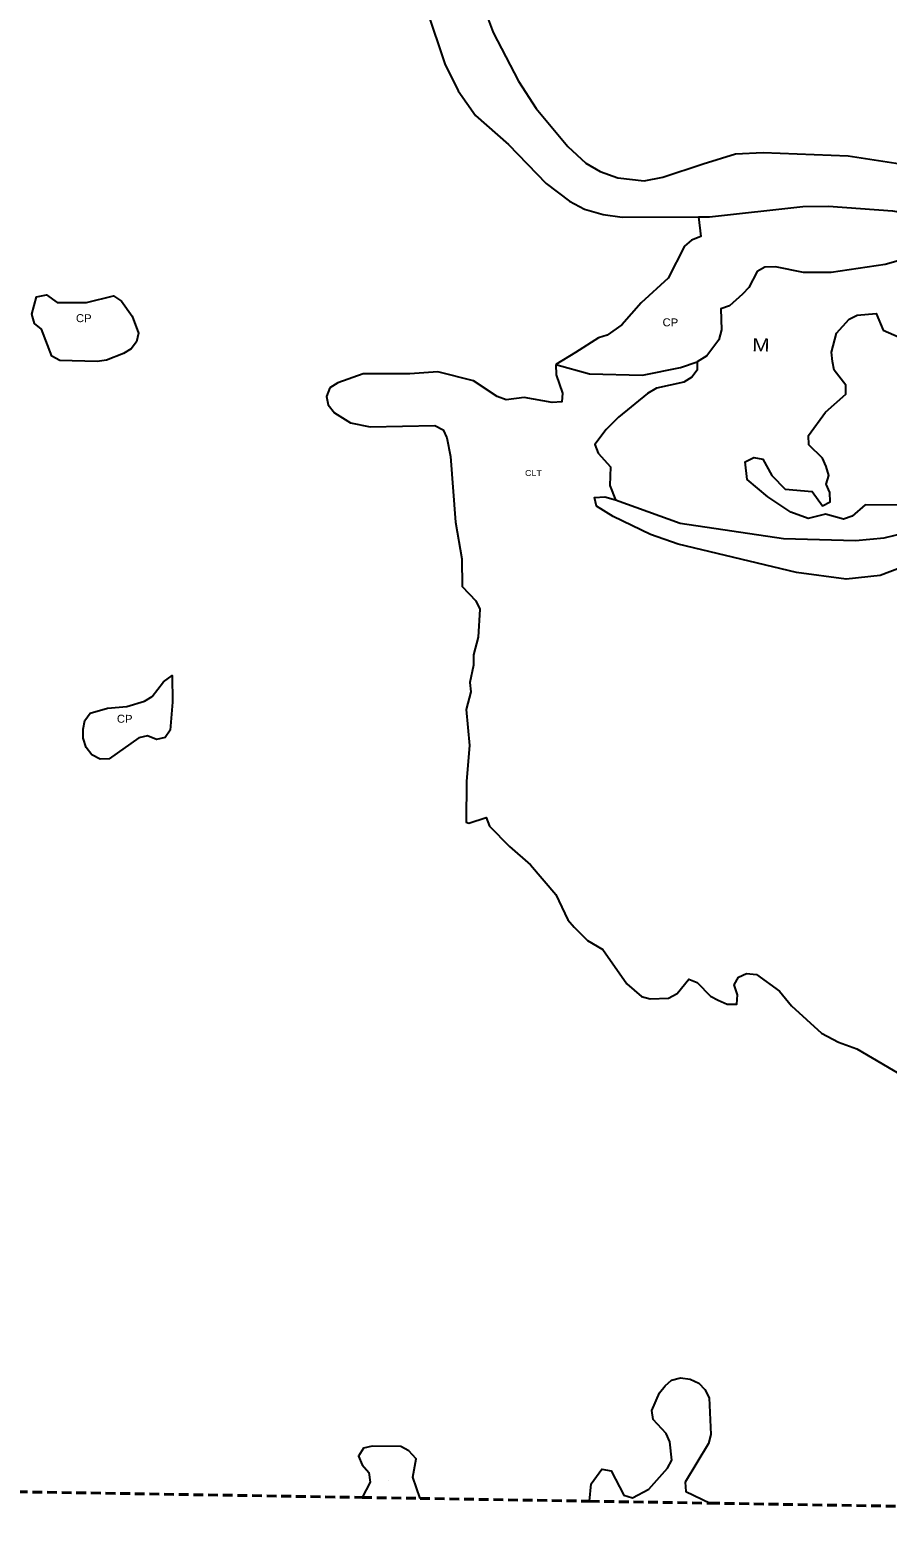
# Model space of a CAD drawing. Extents: x 713589 to 726391, y 7177764 to 7191819.
# Drawn here: x 720180 to 720865, y 7177844 to 7179033 of the extents above; entities that cross this region are included whole.
import ezdxf
from ezdxf.enums import TextEntityAlignment as Align

# ---------------------------------------------------------------- set-up
doc = ezdxf.new("R2010")
doc.units = 0
doc.header["$LTSCALE"] = 2.6
doc.linetypes.add('MEDIUM_DASHED', pattern=[4.5, 3, -1.5])
doc.layers.add('63', color=7, linetype='Continuous', lineweight=25)

msp = doc.modelspace()

# ---------------------------------------------------------------- linework, layer by layer
at = {"layer": '63', "linetype": 'MEDIUM_DASHED', "lineweight": 40}
for p, q in [((720445.89, 7177859.2), (720492.24, 7177858.44)), ((720492.24, 7177858.44), (720627.64, 7177856.21)), ((720627.64, 7177856.21), (720723.8, 7177854.63))]:
    msp.add_line(p, q, dxfattribs=at)
at = {"layer": '63'}
for points in [[(720388.47, 7179333.82), (720393.72, 7179326.74), (720410.66, 7179298.11), (720429.93, 7179253.58), (720435.63, 7179236.95), (720450.29, 7179179.25), (720457.9, 7179155.96), (720477.64, 7179123.9), (720489.24, 7179095.39), (720492.59, 7179082.53), (720497.44, 7179048.39), (720511.9, 7179005.46), (720522.5, 7178983.91), (720536.56, 7178964.26), (720562.68, 7178941.09), (720592.85, 7178909.74), (720611.55, 7178895.61), (720623.58, 7178889.34), (720638.49, 7178884.92), (720653.63, 7178882.96), (720714.47, 7178883.17)], [(720529.81, 7179086.36), (720550.52, 7179030.59), (720570.79, 7178991.72), (720585.01, 7178969.7), (720610.11, 7178939.38), (720624.63, 7178925.98), (720636.04, 7178919.32), (720650.2, 7178914.42), (720671.23, 7178911.99), (720686.07, 7178915.02), (720718.28, 7178925.57), (720744.17, 7178933.45), (720766.28, 7178934.7), (720834.12, 7178932.02), (720903.32, 7178921.4)], [(720714.47, 7178883.17), (720723.47, 7178883.2), (720797.97, 7178891.36), (720818.52, 7178891.73), (720869.63, 7178887.9), (720964.25, 7178871.72), (720986.21, 7178866.68)], [(720714.47, 7178883.17), (720716.4, 7178867.51), (720709.05, 7178864.62), (720703.46, 7178859.69), (720690.29, 7178834.02), (720668.9, 7178814.28), (720653.43, 7178796.84), (720641.58, 7178788.62), (720634.67, 7178786.32), (720616.24, 7178774.8), (720600.6, 7178765.02)], [(720877.86, 7178849.06), (720863.71, 7178845.12), (720820.6, 7178838.54), (720798.55, 7178838.55), (720776.18, 7178843.16), (720767.62, 7178842.83), (720761.37, 7178839.54), (720754.78, 7178826.71), (720749.85, 7178821.44), (720739.32, 7178811.9), (720732.31, 7178809.65), (720732.99, 7178792.88), (720730.88, 7178784.83), (720721.36, 7178772.05), (720713.62, 7178767.32)], [(720877.83, 7178652.61), (720847.88, 7178652.94), (720837.35, 7178643.73), (720830.44, 7178641.43), (720815.96, 7178645.38), (720802.14, 7178642.09), (720788.32, 7178647.03), (720769.89, 7178659.21), (720753.44, 7178673.03), (720751.8, 7178687.18), (720758.71, 7178690.8), (720765.95, 7178689.48), (720773.19, 7178676.32), (720783.71, 7178665.46), (720805.43, 7178663.48), (720813.66, 7178651.96), (720819.91, 7178655.25), (720819.58, 7178662.82), (720816.62, 7178669.4), (720818.6, 7178676.31), (720816.63, 7178683.55), (720813.66, 7178690.13), (720802.81, 7178700.99), (720802.48, 7178708.23), (720815.97, 7178726.99), (720832.43, 7178741.46), (720832.43, 7178748.7), (720822.89, 7178760.55), (720821.58, 7178767.46), (720820.92, 7178775.03), (720824.87, 7178790.17), (720835.07, 7178801.35), (720841.33, 7178804.64), (720856.46, 7178805.96), (720862.06, 7178792.46), (720874.89, 7178786.87)], [(720600.6, 7178765.02), (720627.61, 7178757.74), (720669.75, 7178756.65), (720700.29, 7178762.62), (720713.62, 7178767.32)], [(720713.62, 7178767.32), (720713.64, 7178760.57), (720709.36, 7178754.98), (720702.78, 7178751.03), (720681.06, 7178746.1), (720673.82, 7178741.82), (720650.78, 7178723.07), (720640.91, 7178713.2), (720631.69, 7178701.02), (720634.32, 7178694.11), (720644.19, 7178683.25), (720643.86, 7178668.44), (720648.37, 7178656.9)], [(720600.6, 7178765.02), (720600.77, 7178756.71), (720606.03, 7178742.23), (720605.37, 7178735.32), (720597.8, 7178734.66), (720575.43, 7178738.61), (720560.95, 7178736.97), (720553.71, 7178739.6), (720534.95, 7178752.11), (720506.32, 7178759.36), (720483.95, 7178757.71), (720446.76, 7178757.72), (720426.36, 7178750.49), (720420.11, 7178746.54), (720417.47, 7178739.63), (720418.79, 7178732.72), (720423.72, 7178726.46), (720436.55, 7178718.56), (720452.35, 7178715.27), (720504.01, 7178716.25), (720510.59, 7178712.96), (720513.55, 7178706.37), (720516.51, 7178691.57), (720520.45, 7178638.91), (720525.38, 7178609.63), (720525.71, 7178587.58), (720536.57, 7178576.06), (720539.86, 7178569.48), (720538.54, 7178547.1), (720534.91, 7178532.95), (720534.91, 7178524.72), (720531.95, 7178510.9), (720532.61, 7178503.33), (720528.98, 7178489.19), (720531.61, 7178460.56), (720529.3, 7178431.93), (720528.84, 7178399.03), (720531.23, 7178398.47), (720545.08, 7178402.91), (720547.72, 7178396.06), (720563.52, 7178379.6), (720580.3, 7178365.12), (720600.69, 7178341.42), (720610.23, 7178321.02), (720615.17, 7178315.09), (720626.03, 7178304.56), (720638.2, 7178297.32), (720657.28, 7178270), (720669.13, 7178259.8), (720676.04, 7178257.82), (720690.52, 7178258.48), (720697.43, 7178262.1), (720706.97, 7178273.61), (720713.55, 7178270.98), (720724.08, 7178260.12), (720730.33, 7178256.83), (720737.57, 7178253.53), (720745.14, 7178253.53), (720745.8, 7178261.1), (720743.17, 7178269), (720746.46, 7178275.25), (720753.04, 7178278.21), (720760.94, 7178277.22), (720779.37, 7178264.06), (720788.91, 7178252.21), (720812.93, 7178230.49), (720826.42, 7178223.24), (720841.22, 7178217.98), (720911.31, 7178176.5)], [(720648.37, 7178656.9), (720699.87, 7178638.31), (720782.52, 7178625.9), (720839.92, 7178624.38), (720862.86, 7178626.5), (720880.55, 7178630.66), (720906.83, 7178641.82), (720940.38, 7178663.42), (720951.11, 7178676.1), (720961.89, 7178692.53), (720978.52, 7178727.55)], [(720978.96, 7178667.46), (720976.01, 7178662.75), (720953.52, 7178635.15), (720930.04, 7178623.09), (720859.75, 7178596.36), (720832.57, 7178593.42), (720792.82, 7178598.72), (720698.42, 7178621.36), (720676.28, 7178629.18), (720646.51, 7178643.63), (720633.21, 7178651.81), (720631.45, 7178658.82), (720639.7, 7178659.23), (720648.37, 7178656.9)], [(720627.64, 7177856.21), (720628.91, 7177870.19), (720637.47, 7177881.7), (720644.71, 7177880.38), (720654.91, 7177860.97), (720661.82, 7177858.99), (720674.98, 7177865.9), (720689.79, 7177882.68), (720693.41, 7177888.93), (720691.77, 7177903.74), (720688.81, 7177910.32), (720678.28, 7177921.51), (720677.3, 7177928.75), (720683.55, 7177942.9), (720687.83, 7177948.49), (720693.1, 7177953.1), (720700.33, 7177954.74), (720707.9, 7177953.76), (720714.81, 7177950.46), (720719.75, 7177945.53), (720723.04, 7177938.94), (720724.35, 7177909.66), (720722.7, 7177902.42), (720703.94, 7177871.49), (720704.6, 7177863.92), (720723.8, 7177854.63)], [(720492.24, 7177858.44), (720486.43, 7177875.48), (720489.06, 7177889.95), (720483.14, 7177896.54), (720476.89, 7177899.83), (720453.85, 7177900.16), (720446.94, 7177898.52), (720442.99, 7177892.27), (720445.95, 7177885.36), (720451.22, 7177879.1), (720452.2, 7177871.53), (720445.89, 7177859.2)]]:
    msp.add_lwpolyline(points, dxfattribs=at)
for points in [[(720234.06, 7178767.56), (720204.44, 7178768.23), (720197.86, 7178771.85), (720189.64, 7178793.24), (720184.05, 7178797.85), (720182.07, 7178805.42), (720185.7, 7178819.24), (720193.59, 7178820.88), (720202.24, 7178814.63), (720225.51, 7178814.62), (720247.23, 7178819.88), (720253.48, 7178815.61), (720262.04, 7178803.76), (720267.3, 7178790.26), (720265.65, 7178783.35), (720261.38, 7178777.76), (720255.12, 7178773.81), (720241.63, 7178768.55)], [(720225.25, 7178458.96), (720222.94, 7178466.2), (720222.94, 7178473.44), (720224.26, 7178480.35), (720228.54, 7178486.28), (720242.36, 7178490.22), (720257.83, 7178491.54), (720271.98, 7178495.81), (720278.23, 7178499.76), (720287.12, 7178511.28), (720294.05, 7178516.47), (720294.36, 7178495.15), (720292.38, 7178472.77), (720288.43, 7178466.85), (720281.52, 7178465.21), (720274.28, 7178468.17), (720267.37, 7178466.53), (720243.67, 7178449.75), (720236.43, 7178449.42), (720229.85, 7178453.04)]]:
    msp.add_lwpolyline(points, close=True, dxfattribs=at)
at = {"layer": '63', "linetype": 'MEDIUM_DASHED', "lineweight": 40}
for points in [[(720108.51, 7177864.75), (720135.62, 7177864.3), (720445.89, 7177859.2)], [(720723.8, 7177854.63), (721307.76, 7177845.02), (721360.74, 7177844.15)]]:
    msp.add_lwpolyline(points, dxfattribs=at)

# ---------------------------------------------------------------- texts
at = {"layer": '63'}
for s, height, width, p in [('CP', 6.4, 1.05, (720223.4, 7178798.92)), ('CP', 6.4, 1.05, (720692.07, 7178795.59)), ('M', 10.4, 1.2, (720764.37, 7178775.57)), ('CLT', 4.64, 1.15, (720582.71, 7178675.97)), ('CP', 6.4, 1.05, (720256.1, 7178478.61)), ('CP', 0.32, 1.05, (720700.97, 7177890.12)), ('CP', 0.32, 1.05, (720467.12, 7177872.58))]:
    msp.add_text(s, height=height, rotation=359.062, dxfattribs=dict(at, width=width)).set_placement(p, align=Align.CENTER)

doc.saveas('drawing.dxf')
